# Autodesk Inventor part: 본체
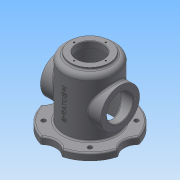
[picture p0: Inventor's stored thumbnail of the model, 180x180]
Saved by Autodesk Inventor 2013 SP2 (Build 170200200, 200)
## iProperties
Created: 2026-07
Part Number: 본체
Material: Generic
Document SubType Name: Modeling
Designer: a
Density: 1 g/cm^3
Author: a
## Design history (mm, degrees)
sketch "스케치1"
  geometry: A1 r 30 centre (-100, 0) between (-79.12, -21.541) and (-79.12, 21.541); A2 r 30 centre (0, -100) between (21.541, -79.12) and (-21.541, -79.12); A3 r 30 centre (100, 0) between (79.12, 21.541) and (79.12, -21.541); A4 r 30 centre (0, 100) between (-21.541, 79.12) and (21.541, 79.12); A5 r 82 centre (0, 0) between (-79.12, -21.541) and (-21.541, -79.12); A6 r 82 centre (0, 0) between (21.541, -79.12) and (79.12, -21.541); A7 r 82 centre (0, 0) between (79.12, 21.541) and (21.541, 79.12); A8 r 82 centre (0, 0) between (-21.541, 79.12) and (-79.12, 21.541); 1 further point
  constraints: 16 point on circle, 8 centre point, 1 coincident, 1 horizontal alignment, 17 other
  dimensions: "d2" = 30 radius of A1; "d3" = 100 distance of A1.centre point (0, 0); "d6" = 360 deg dimension on point (0, 0) A1.centre (derived); "d8" = 82 radius of A6
extrude "돌출1" new body sketch "스케치1" distance "d9" = 14; taper "d10" = 0 deg
sketch "스케치3"
  geometry: C1 r 53 at (0, 0); A1 r 82 centre (0, 0) between (79.12, 21.541) and (21.541, 79.12) reference
  constraints: 1 centre point, 1 coincident
  dimensions: "d15" = 53 radius of C1
extrude "돌출2" join sketch "스케치3" distance "d16" = 118; taper "d17" = 0 deg
sketch "스케치4"
  geometry: C1 r 53 at (0, 0) reference; C2 r 40 at (0, 0)
  constraints: 1 centre point, 1 coincident
  dimensions: "d18" = 40 radius of C2
extrude "돌출3" join sketch "스케치4" distance "d19" = 5; taper "d20" = 0 deg
sketch "스케치5"
  geometry: C1 r 40 at (68, 0); 1 further point
  constraints: 1 centre point, 1 horizontal alignment
  dimensions: "d21" = 40 radius of C1; "d22" = 68 distance of point (0, 0) C1.centre
extrude "돌출4" join sketch "스케치5" stored distance "d23" = 124; taper "d24" = 0 deg
sketch "스케치6"
  geometry: C1 r 45 at (0, 0); A1 r 82 centre (0, 0) between (21.541, -79.12) and (79.12, -21.541) reference
  constraints: 1 centre point, 1 coincident
  dimensions: "d25" = 45 radius of C1
extrude "돌출5" cut sketch "스케치6" distance "d26" = 124; taper "d27" = 0 deg
sketch "스케치7"
  geometry: C1 r 45 at (0, 0) reference; C2 r 27 at (0, 0)
  constraints: 1 centre point, 1 coincident
  dimensions: "d28" = 27 radius of C2
extrude "돌출6" cut sketch "스케치7" stored distance "d29" = 124; taper "d30" = 0 deg
sketch "스케치8"
  geometry: C1 r 27 at (0, 0) reference; 1 further point
  constraints: 1 vertical alignment
  dimensions: "d31" = 32.5 distance of C1.centre point (0, 32.5)
hole "구멍1" sketch "스케치8" at (0, 32.5) diameter "d32" = 3.242; stored, may be unused: countersink angle "d36" = 90 deg, drill point angle "d38" = 118 deg; dims "d33" = 8, "d34" = 4, "d35" = 2, "d37" = 10
sketch "스케치9"
  geometry: C1 r 40 at (0, 0) reference; C2 r 27 at (0, 0); 1 further point
  constraints: 1 centre point, 1 coincident
  dimensions: "d42" = 27 radius of C2
extrude "돌출7" cut sketch "스케치9" stored distance "d43" = 124; taper "d44" = 0 deg
sketch "스케치10"
  geometry: C1 r 27 at (0, 0) reference; 2 further points
  constraints: 1 vertical alignment
  dimensions: "d45" = 32.5 distance of C1.centre point (0, 32.5)
hole "구멍2" sketch "스케치10" at (0, 32.5) diameter "d46" = 3.242; stored, may be unused: countersink angle "d50" = 90 deg, drill point angle "d52" = 118 deg; dims "d47" = 8, "d48" = 4, "d49" = 2, "d51" = 10
sketch "스케치11"
  geometry: L1 (0, 0)-(47.73, 47.73); L2 (0, 0)-(67.5, 0); C1 r 53 at (0, 0) reference; C2 r 67.5 at (0, 0); C3 r 4.5 at (47.73, 47.73)
  constraints: 4 end point, 3 coincident, 2 centre point, 1 equal length, 1 horizontal
  dimensions: "d56" = 67.5 radius of C2; "d57" = 67.5 distance of L1.start L1.end; "d58" = 45 deg angle of L2 L1; "d59" = 4.5 radius of C3
extrude "돌출8" cut sketch "스케치11" stored distance "d60" = 124; taper "d61" = 0 deg
fillet "모깎기1" dims "d65" = 10
fillet "모깎기2" dims "d66" = 3
chamfer "모따기1" distance "d67" = 1; stored, may be unused: second distance "d68" = 2, angle "d69" = 45 deg
fillet "모깎기3" dims "d70" = 3
node "작업 평면1"
sketch "스케치12"
  geometry: 2 further points
  constraints: 1 vertical alignment, 1 other
  dimensions: "d72" = 70 distance of point (0, 70) point (0, 0)
feature "엠보싱1" sketch "스케치12" dims "d4" = 40, "d73" = 0.5, "d74" = 0
node "솔리드1"
pattern_circular "원형 패턴1" dims angle "d40" = 360 deg
pattern_circular "원형 패턴2" dims angle "d54" = 360 deg
mirror "대칭1"
pattern_circular "원형 패턴3" dims angle "d63" = 360 deg
other parameters: "d0" = 82, "d71" = 81
